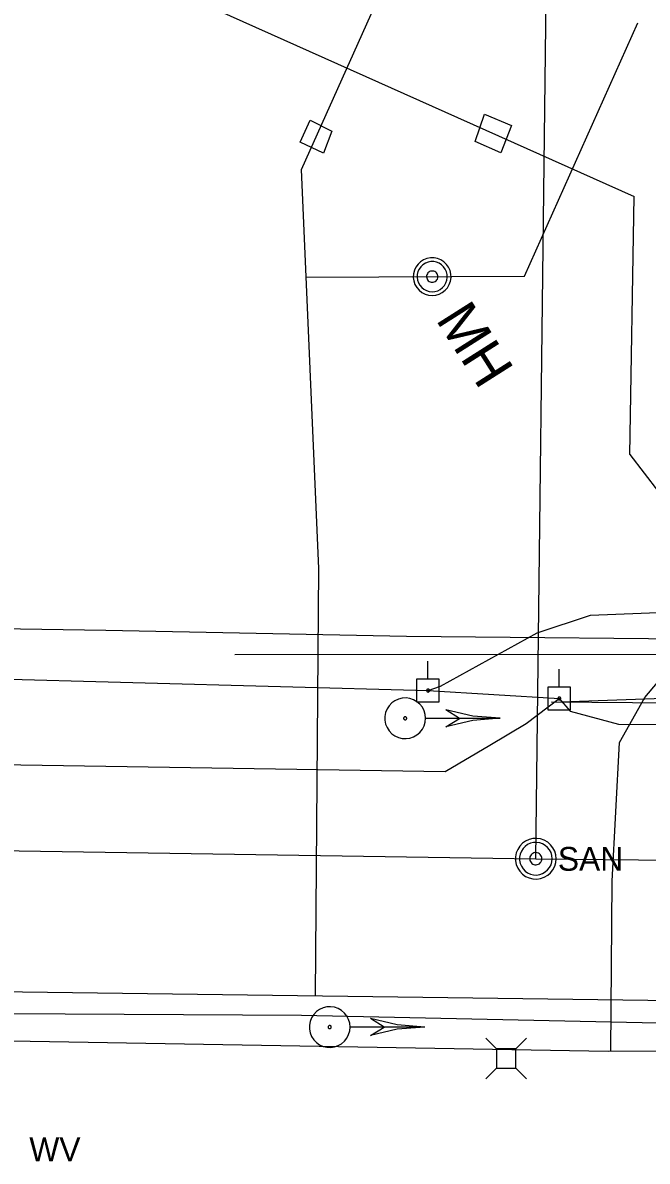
# Model space of a CAD drawing. Extents: x 596028 to 606371, y 330010 to 403088.
# Drawn here: x 604654.3 to 604755.5, y 332666.3 to 332850.6 of the extents above; entities that cross this region are included whole.
import ezdxf

# ---------------------------------------------------------------- set-up
doc = ezdxf.new("R2010")
doc.units = 0
for name, color, linetype in [('E_SIG', 7, 'Continuous'), ('E_UTL_E_UG', 7, 'Continuous'), ('E_UTL_EGuyWire', 7, 'Continuous'), ('E_UTL_EPowerPole', 7, 'Continuous'), ('E_UTL_FO_UG_MCI', 7, 'Continuous'), ('E_UTL_G_UG', 7, 'Continuous'), ('E_UTL_Overhead', 7, 'Continuous'), ('E_UTL_SAN_MH', 7, 'Continuous'), ('E_UTL_SAN_UG', 7, 'Continuous'), ('E_UTL_T', 7, 'Continuous'), ('E_UTL_T_UG', 7, 'Continuous'), ('E_UTL_TV_UG', 7, 'Continuous'), ('E_UTL_W', 7, 'Continuous'), ('E_UTL_W_MH', 7, 'Continuous'), ('E_UTL_W_UG', 7, 'Continuous')]:
    doc.layers.add(name, color=color, linetype=linetype)

msp = doc.modelspace()

# ---------------------------------------------------------------- linework, layer by layer
at = {"layer": 'E_SIG'}
for points in [[(604719.58, 332738.02), (604719.52, 332738.64), (604719.34, 332739.24), (604719.06, 332739.8), (604718.67, 332740.29), (604718.19, 332740.7), (604717.65, 332741.02), (604717.06, 332741.22), (604716.44, 332741.31), (604715.81, 332741.28), (604715.2, 332741.13), (604714.63, 332740.87), (604714.12, 332740.51), (604713.68, 332740.06), (604713.35, 332739.53), (604713.11, 332738.95), (604712.99, 332738.33), (604712.99, 332737.7), (604713.11, 332737.09), (604713.35, 332736.5), (604713.68, 332735.98), (604714.12, 332735.52), (604714.63, 332735.16), (604715.2, 332734.9), (604715.81, 332734.75), (604716.44, 332734.72), (604717.06, 332734.81), (604717.65, 332735.01), (604718.19, 332735.33), (604718.67, 332735.74), (604719.06, 332736.23), (604719.34, 332736.79), (604719.52, 332737.39), (604719.58, 332738.02)], [(604716.53, 332738.02), (604716.53, 332738.06), (604716.51, 332738.11), (604716.49, 332738.15), (604716.46, 332738.19), (604716.43, 332738.22), (604716.38, 332738.25), (604716.34, 332738.26), (604716.29, 332738.27), (604716.24, 332738.27), (604716.2, 332738.25), (604716.15, 332738.23), (604716.11, 332738.21), (604716.08, 332738.17), (604716.05, 332738.13), (604716.04, 332738.09), (604716.03, 332738.04), (604716.03, 332737.99), (604716.04, 332737.94), (604716.05, 332737.9), (604716.08, 332737.86), (604716.11, 332737.83), (604716.15, 332737.8), (604716.2, 332737.78), (604716.24, 332737.77), (604716.29, 332737.76), (604716.34, 332737.77), (604716.38, 332737.79), (604716.43, 332737.81), (604716.46, 332737.84), (604716.49, 332737.88), (604716.51, 332737.92), (604716.53, 332737.97), (604716.53, 332738.02)], [(604731.68, 332738.01), (604719.64, 332738.01)], [(604731.68, 332738.02), (604727.23, 332738.36), (604722.88, 332739.39)], [(604725.08, 332738.01), (604722.88, 332739.39)], [(604731.68, 332738.02), (604727.23, 332737.67), (604722.88, 332736.64)], [(604722.88, 332736.64), (604725.08, 332738.01)], [(604707.36, 332688.01), (604707.3, 332688.64), (604707.12, 332689.24), (604706.83, 332689.8), (604706.45, 332690.29), (604705.97, 332690.7), (604705.43, 332691.01), (604704.84, 332691.22), (604704.21, 332691.31), (604703.59, 332691.28), (604702.98, 332691.13), (604702.41, 332690.87), (604701.9, 332690.51), (604701.46, 332690.05), (604701.12, 332689.52), (604700.89, 332688.94), (604700.77, 332688.33), (604700.77, 332687.7), (604700.89, 332687.08), (604701.12, 332686.5), (604701.46, 332685.97), (604701.9, 332685.52), (604702.41, 332685.15), (604702.98, 332684.89), (604703.59, 332684.75), (604704.21, 332684.72), (604704.84, 332684.81), (604705.43, 332685.01), (604705.97, 332685.32), (604706.45, 332685.73), (604706.83, 332686.23), (604707.12, 332686.79), (604707.3, 332687.39), (604707.36, 332688.01)], [(604704.31, 332688.01), (604704.31, 332688.06), (604704.29, 332688.11), (604704.27, 332688.15), (604704.24, 332688.19), (604704.2, 332688.22), (604704.16, 332688.24), (604704.12, 332688.26), (604704.07, 332688.26), (604704.02, 332688.26), (604703.98, 332688.25), (604703.93, 332688.23), (604703.89, 332688.2), (604703.86, 332688.17), (604703.83, 332688.13), (604703.82, 332688.08), (604703.81, 332688.04), (604703.81, 332687.99), (604703.82, 332687.94), (604703.83, 332687.9), (604703.86, 332687.86), (604703.89, 332687.82), (604703.93, 332687.79), (604703.98, 332687.77), (604704.02, 332687.76), (604704.07, 332687.76), (604704.12, 332687.77), (604704.16, 332687.78), (604704.2, 332687.81), (604704.24, 332687.84), (604704.27, 332687.88), (604704.29, 332687.92), (604704.31, 332687.96), (604704.31, 332688.01)], [(604719.46, 332688.01), (604715, 332688.36), (604710.66, 332689.39)], [(604712.86, 332688.01), (604710.66, 332689.39)], [(604719.46, 332688.01), (604707.42, 332688.01)], [(604719.46, 332688.01), (604715, 332687.67), (604710.66, 332686.64)], [(604710.66, 332686.64), (604712.86, 332688.01)]]:
    msp.add_lwpolyline(points, dxfattribs=at)
at = {"layer": 'E_UTL_E_UG'}
for points in [[(604729.97, 332733.67), (604735.89, 332737.18), (604741.23, 332741.22), (604743.03, 332739.17), (604750.82, 332737.08), (604770.44, 332736.98), (604808.3, 332737.08), (604829.69, 332734.9), (604883.87, 332734.01), (604905.84, 332733.85), (604937.84, 332733.34), (604976.01, 332733.17), (605006.49, 332733.09)], [(604416.96, 332734.23), (604722.78, 332729.41), (604729.97, 332733.67)]]:
    msp.add_lwpolyline(points, dxfattribs=at)
at = {"layer": 'E_UTL_EGuyWire'}
msp.add_line((604770.31, 332740.41), (604740, 332740.64), dxfattribs=at)
at = {"layer": 'E_UTL_EPowerPole'}
for points in [[(604719.96, 332744.35), (604719.96, 332747.26)], [(604741.23, 332743.06), (604741.23, 332745.97)], [(604721.8, 332744.35), (604718.11, 332744.35)], [(604718.11, 332744.35), (604718.11, 332740.66)], [(604721.8, 332740.66), (604721.8, 332744.35)], [(604720.23, 332742.51), (604720.22, 332742.56), (604720.21, 332742.6), (604720.19, 332742.64), (604720.16, 332742.68), (604720.13, 332742.71), (604720.09, 332742.73), (604720.05, 332742.74), (604720, 332742.75), (604719.96, 332742.75), (604719.91, 332742.74), (604719.87, 332742.72), (604719.83, 332742.69), (604719.8, 332742.66), (604719.78, 332742.62), (604719.76, 332742.58), (604719.75, 332742.53), (604719.75, 332742.49), (604719.76, 332742.44), (604719.78, 332742.4), (604719.8, 332742.36), (604719.83, 332742.33), (604719.87, 332742.3), (604719.91, 332742.29), (604719.96, 332742.27), (604720, 332742.27), (604720.05, 332742.28), (604720.09, 332742.29), (604720.13, 332742.32), (604720.16, 332742.35), (604720.19, 332742.38), (604720.21, 332742.42), (604720.22, 332742.47), (604720.23, 332742.51)], [(604743.07, 332743.06), (604739.39, 332743.06)], [(604739.39, 332743.06), (604739.39, 332739.37)], [(604743.07, 332739.37), (604743.07, 332743.06)], [(604718.11, 332740.66), (604721.8, 332740.66)], [(604741.5, 332741.22), (604741.5, 332741.26), (604741.48, 332741.31), (604741.46, 332741.35), (604741.43, 332741.38), (604741.4, 332741.41), (604741.36, 332741.43), (604741.32, 332741.45), (604741.27, 332741.46), (604741.23, 332741.45), (604741.18, 332741.44), (604741.14, 332741.42), (604741.11, 332741.4), (604741.07, 332741.37), (604741.05, 332741.33), (604741.03, 332741.29), (604741.02, 332741.24), (604741.02, 332741.2), (604741.03, 332741.15), (604741.05, 332741.11), (604741.07, 332741.07), (604741.11, 332741.04), (604741.14, 332741.01), (604741.18, 332740.99), (604741.23, 332740.98), (604741.27, 332740.98), (604741.32, 332740.99), (604741.36, 332741), (604741.4, 332741.02), (604741.43, 332741.05), (604741.46, 332741.09), (604741.48, 332741.13), (604741.5, 332741.17), (604741.5, 332741.22)], [(604739.39, 332739.37), (604743.07, 332739.37)]]:
    msp.add_lwpolyline(points, dxfattribs=at)
at = {"layer": 'E_UTL_FO_UG_MCI'}
msp.add_line((604688.68, 332748.34), (605019.17, 332748.55), dxfattribs=at)
at = {"layer": 'E_UTL_G_UG'}
msp.add_line((604453.34, 332696.36), (605095.21, 332687.86), dxfattribs=at)
msp.add_line((604453.34, 332696.36), (605095.21, 332687.86), dxfattribs=at)
for points in [[(604749.57, 332684.13), (604749.82, 332711.64), (604750.99, 332734.1), (604755.08, 332741.37), (604772.31, 332761.79)], [(604515.1, 332688.18), (604749.17, 332684.11), (604776.51, 332684.21)]]:
    msp.add_lwpolyline(points, dxfattribs=at)
at = {"layer": 'E_UTL_Overhead'}
msp.add_line((604740, 332740.64), (604834.23, 332743.9), dxfattribs=at)
msp.add_lwpolyline([(604303.82, 332747.1), (604303.82, 332750.1), (604395.83, 332752.41), (604557.99, 332749.19), (604648.21, 332744.48), (604719.99, 332742.51), (604741.26, 332741.22)], dxfattribs=at)
at = {"layer": 'E_UTL_SAN_MH'}
for points in [[(604740.74, 332715.28), (604740.68, 332715.9), (604740.51, 332716.5), (604740.22, 332717.06), (604739.83, 332717.55), (604739.36, 332717.97), (604738.82, 332718.28), (604738.22, 332718.48), (604737.6, 332718.57), (604736.97, 332718.54), (604736.36, 332718.4), (604735.79, 332718.14), (604735.28, 332717.77), (604734.85, 332717.32), (604734.51, 332716.79), (604734.28, 332716.21), (604734.16, 332715.59), (604734.16, 332714.96), (604734.28, 332714.35), (604734.51, 332713.77), (604734.85, 332713.24), (604735.28, 332712.78), (604735.79, 332712.42), (604736.36, 332712.16), (604736.97, 332712.01), (604737.6, 332711.98), (604738.22, 332712.07), (604738.82, 332712.28), (604739.36, 332712.59), (604739.83, 332713), (604740.22, 332713.49), (604740.51, 332714.05), (604740.68, 332714.65), (604740.74, 332715.28)], [(604740.08, 332715.28), (604740.04, 332715.78), (604739.9, 332716.26), (604739.67, 332716.71), (604739.35, 332717.1), (604738.98, 332717.43), (604738.54, 332717.68), (604738.07, 332717.84), (604737.57, 332717.91), (604737.07, 332717.89), (604736.58, 332717.77), (604736.12, 332717.56), (604735.72, 332717.27), (604735.37, 332716.91), (604735.1, 332716.49), (604734.91, 332716.02), (604734.82, 332715.53), (604734.82, 332715.03), (604734.91, 332714.53), (604735.1, 332714.07), (604735.37, 332713.65), (604735.72, 332713.28), (604736.12, 332712.99), (604736.58, 332712.78), (604737.07, 332712.66), (604737.57, 332712.64), (604738.07, 332712.71), (604738.54, 332712.88), (604738.98, 332713.13), (604739.35, 332713.46), (604739.67, 332713.85), (604739.9, 332714.3), (604740.04, 332714.78), (604740.08, 332715.28)], [(604738.43, 332715.28), (604738.42, 332715.47), (604738.36, 332715.65), (604738.28, 332715.81), (604738.16, 332715.96), (604738.02, 332716.08), (604737.86, 332716.18), (604737.68, 332716.24), (604737.49, 332716.27), (604737.3, 332716.26), (604737.12, 332716.21), (604736.95, 332716.14), (604736.8, 332716.03), (604736.67, 332715.89), (604736.56, 332715.73), (604736.49, 332715.56), (604736.46, 332715.37), (604736.46, 332715.18), (604736.49, 332715), (604736.56, 332714.82), (604736.67, 332714.67), (604736.8, 332714.53), (604736.95, 332714.42), (604737.12, 332714.34), (604737.3, 332714.3), (604737.49, 332714.29), (604737.68, 332714.32), (604737.86, 332714.38), (604738.02, 332714.47), (604738.16, 332714.59), (604738.28, 332714.74), (604738.36, 332714.91), (604738.42, 332715.09), (604738.43, 332715.28)]]:
    msp.add_lwpolyline(points, dxfattribs=at)
at = {"layer": 'E_UTL_SAN_UG'}
for p, q in [((604737.44, 332715.28), (604740.67, 332982.57)), ((604426.3, 332720.08), (604737.44, 332715.28)), ((604737.44, 332715.28), (604982.83, 332712.71))]:
    msp.add_line(p, q, dxfattribs=at)
at = {"layer": 'E_UTL_T'}
for points in [[(604731.09, 332684.47), (604729.34, 332686.22)], [(604734.19, 332684.47), (604731.09, 332684.47)], [(604731.09, 332684.47), (604731.09, 332681.37)], [(604734.19, 332684.47), (604735.94, 332686.22)], [(604734.19, 332681.37), (604734.19, 332684.47)], [(604731.09, 332681.37), (604729.34, 332679.62)], [(604731.09, 332681.37), (604734.19, 332681.37)], [(604734.19, 332681.37), (604735.94, 332679.62)]]:
    msp.add_lwpolyline(points, dxfattribs=at)
at = {"layer": 'E_UTL_T_UG'}
msp.add_lwpolyline([(604626.24, 332752.96), (604667.79, 332752.28), (604716.52, 332751.29), (604772.47, 332750.78), (604802.28, 332745.13), (604821.11, 332741.83), (604839.24, 332737.01), (604851.39, 332734.26), (604870.7, 332730.27), (604882.93, 332728.13), (604900.25, 332727.49), (604950.98, 332727.08), (604995.39, 332726.29), (605022.19, 332726.03), (605084.56, 332725.74), (605114.2, 332728.34), (605148.01, 332733.35)], dxfattribs=at)
at = {"layer": 'E_UTL_TV_UG'}
msp.add_lwpolyline([(604719.99, 332742.51), (604722.02, 332743.2), (604737.64, 332751.88), (604746.32, 332754.74), (604758.63, 332755.19), (604777.9, 332753.87), (604804.51, 332750.48), (604825.34, 332746.4), (604832.2, 332741.86), (604839.54, 332740.05), (604839.79, 332740.1), (604863.7, 332738.45), (604885.99, 332737.63), (604916.23, 332736.12)], dxfattribs=at)
at = {"layer": 'E_UTL_W_MH'}
for points in [[(604729.14, 332835.84), (604733.5, 332834.01), (604731.77, 332829.6), (604727.62, 332831.44)], [(604700.87, 332834.88), (604704.41, 332833.12), (604703.06, 332829.55), (604699.27, 332831.3)]]:
    msp.add_lwpolyline(points, close=True, dxfattribs=at)
for points in [[(604722.29, 332806.96), (604722.75, 332807.32), (604723.14, 332807.75), (604723.43, 332808.25), (604723.62, 332808.8), (604723.71, 332809.38), (604723.68, 332809.96), (604723.55, 332810.52), (604723.31, 332811.05), (604722.98, 332811.53), (604722.56, 332811.93), (604722.07, 332812.25), (604721.54, 332812.47), (604720.97, 332812.58), (604720.38, 332812.58), (604719.81, 332812.48), (604719.27, 332812.26), (604718.78, 332811.95), (604718.36, 332811.55), (604718.02, 332811.08), (604717.78, 332810.56), (604717.64, 332809.99), (604717.6, 332809.41), (604717.68, 332808.84), (604717.87, 332808.29), (604718.16, 332807.78), (604718.54, 332807.34), (604718.99, 332806.98), (604719.51, 332806.71), (604720.06, 332806.54), (604720.64, 332806.48), (604721.22, 332806.54), (604721.78, 332806.7), (604722.29, 332806.96)], [(604721.97, 332807.48), (604722.33, 332807.76), (604722.64, 332808.11), (604722.88, 332808.51), (604723.03, 332808.95), (604723.1, 332809.41), (604723.08, 332809.87), (604722.97, 332810.33), (604722.78, 332810.75), (604722.51, 332811.13), (604722.18, 332811.45), (604721.79, 332811.71), (604721.36, 332811.88), (604720.9, 332811.97), (604720.44, 332811.97), (604719.98, 332811.89), (604719.55, 332811.72), (604719.16, 332811.47), (604718.82, 332811.15), (604718.55, 332810.77), (604718.35, 332810.35), (604718.24, 332809.9), (604718.22, 332809.44), (604718.28, 332808.98), (604718.43, 332808.54), (604718.66, 332808.13), (604718.96, 332807.78), (604719.32, 332807.49), (604719.74, 332807.28), (604720.18, 332807.14), (604720.64, 332807.09), (604721.11, 332807.14), (604721.55, 332807.26), (604721.97, 332807.48)], [(604721.15, 332808.77), (604721.29, 332808.87), (604721.4, 332809), (604721.49, 332809.15), (604721.55, 332809.32), (604721.57, 332809.49), (604721.57, 332809.66), (604721.53, 332809.83), (604721.45, 332809.99), (604721.35, 332810.14), (604721.23, 332810.26), (604721.08, 332810.35), (604720.92, 332810.42), (604720.75, 332810.45), (604720.58, 332810.45), (604720.4, 332810.42), (604720.24, 332810.36), (604720.1, 332810.26), (604719.97, 332810.14), (604719.87, 332810), (604719.79, 332809.84), (604719.75, 332809.67), (604719.74, 332809.5), (604719.77, 332809.33), (604719.82, 332809.16), (604719.91, 332809.01), (604720.02, 332808.88), (604720.16, 332808.77), (604720.31, 332808.69), (604720.48, 332808.64), (604720.65, 332808.62), (604720.83, 332808.64), (604720.99, 332808.69), (604721.15, 332808.77)]]:
    msp.add_lwpolyline(points, dxfattribs=at)
at = {"layer": 'E_UTL_W_UG'}
for p, q in [((604699.5, 332826.87), (604717.45, 332867)), ((604662.86, 332863.01), (604753.37, 332822.51)), ((604735.63, 332809.59), (604753.99, 332850.65)), ((604702.32, 332762.28), (604699.5, 332826.87)), ((604752.66, 332780.75), (604753.37, 332822.51)), ((604700.26, 332809.47), (604735.63, 332809.59)), ((604752.66, 332780.75), (604833.78, 332675)), ((604701.76, 332693.13), (604702.32, 332762.28))]:
    msp.add_line(p, q, dxfattribs=at)
msp.add_lwpolyline([(604557.89, 332691.73), (604602.99, 332690.99), (604651.65, 332690.22), (604699.51, 332689.92), (604777.25, 332688.26)], dxfattribs=at)

# ---------------------------------------------------------------- texts
at = {"layer": 'E_UTL_SAN_MH'}
msp.add_text('SAN', height=3.849, dxfattribs=at).set_placement((604741.01, 332713.33))
at = {"layer": 'E_UTL_W'}
msp.add_text('WV', height=3.85, dxfattribs=at).set_placement((604655.4, 332666.29))
at = {"layer": 'E_UTL_W_MH'}
msp.add_text('MH', height=6.6, rotation=302.3928, dxfattribs=at).set_placement((604721.14, 332802.61))

doc.saveas('drawing.dxf')
